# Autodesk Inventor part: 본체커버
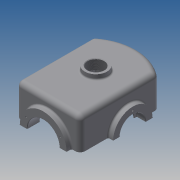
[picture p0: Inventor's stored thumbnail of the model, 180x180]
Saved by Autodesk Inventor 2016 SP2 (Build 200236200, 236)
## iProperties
Created: 2019-03
Part Number: 본체커버
Material: 알루미늄 6061
Document SubType Name: Modeling
Designer: mduedu
Density: 2.71 g/cm^3
Mass: 1472.73 g
Surface Area: 1101.4 cm^2
Volume: 543.443 cm^3
Appearance: 기본값
Author: mduedu
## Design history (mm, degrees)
sketch "스케치1"
  geometry: L1 (90, -65)-(-65.993, -65); L2 (-65.993, 65)-(90, 65); L3 (90, 65)-(90, -65); L4 (-90, 0)-(90, 0); A1 r 100 centre (10, 0) between (-65.993, 65) and (-65.993, -65); 2 further points
  constraints: 8 end point, 3 point on circle, 2 horizontal alignment, 2 midpoint, 1 centre point, 1 coincident, 1 horizontal, 1 parallel, 1 perpendicular
  dimensions: "d0" = 100 radius of A1; "d2" = 180 distance from line of L3 L4.start; "d3" = 130 distance between parallel lines of L2 L1
extrude "돌출1" new body sketch "스케치1" distance "d4" = 65; taper "d5" = 0 deg
fillet "모깎기1" dims "d6" = 10
fillet "모깎기2" dims "d7" = 10
feature "쉘1" dims "d8" = 10, "d79" = 15
fillet "모깎기3" dims "d9" = 3
fillet "모깎기4" dims "d10" = 3
sketch "스케치2"
  geometry: L1 (110, 0)-(0, 0) reference; A1 r 47.5 centre (55, 0) between (102.5, 0) and (7.5, 0); 1 further point
  constraints: 2 point on circle, 2 point on line, 1 centre point, 1 coincident
  dimensions: "d11" = 95 diameter of A1
extrude "돌출2" join sketch "스케치2" distance "d12" = 10; taper "d13" = 0 deg
hole "구멍1" diameter "d16" = 65; stored, may be unused: countersink angle "d20" = 90 deg, drill point angle "d22" = 118 deg; dims "d14" = 10, "d15" = 10, "d17" = 6, "d18" = 4, "d19" = 2, "d21" = 8
node "작업 평면1"
sketch "스케치3"
  geometry: L1 (61.239, 0)-(-80, 0) reference; L2 (-100, 47.5)-(-100, 0) reference; A1 r 40 centre (7, 0) between (47, 0) and (-33, 0); 1 further point
  constraints: 2 point on circle, 2 point on line, 1 centre point, 1 horizontal alignment
  dimensions: "d24" = 80 diameter of A1; "d25" = 107 distance from line of A1.centre L2
extrude "돌출3" join sketch "스케치3" stored distance "d26" = 10; taper "d27" = 0 deg
hole "구멍2" diameter "d30" = 42; stored, may be unused: countersink angle "d34" = 90 deg, drill point angle "d36" = 118 deg; dims "d28" = 10, "d29" = 10, "d31" = 6, "d32" = 52, "d33" = 18, "d35" = 8
sketch "스케치4" dims "d37" = 65
  geometry: A1 r 40 centre (7, 0) between (47, 0) and (-33, 0) reference; 3 further points
  constraints: 2 vertical alignment, 1 coincident, 2 other
hole "구멍3" sketch "스케치4" at (7, 32.5) diameter "d38" = 3.242; stored, may be unused: countersink angle "d42" = 90 deg, drill point angle "d44" = 118 deg; dims "d39" = 11, "d40" = 52, "d41" = 18, "d43" = 13
sketch "스케치5" dims "d45" = 80
  geometry: A1 r 47.5 centre (55, 0) between (102.5, 0) and (7.5, 0) reference; 5 further points
  constraints: 2 vertical alignment, 1 coincident, 6 other
  dimensions: "d48" = 360 deg dimension on point (55, 0) point (55, -40) (derived)
hole "구멍4" sketch "스케치5" at (55, -40), (89.641, 20), (20.359, 20) diameter "d50" = 3.242; stored, may be unused: countersink angle "d54" = 90 deg, drill point angle "d56" = 118 deg; dims "d51" = 11, "d52" = 52, "d53" = 18, "d55" = 13
fillet "모깎기5" dims "d57" = 3
fillet "모깎기6" dims "d58" = 1
chamfer "모따기1" distance "d59" = 1; stored, may be unused: second distance "d60" = 2, angle "d61" = 45 deg
node "작업 평면2"
sketch "스케치6"
  geometry: L1 (-47, 75)-(33, 75) reference; L2 (-47, -75)-(33, -75) reference; L3 (-7, 75)-(-7, -75); C1 r 22.5 at (-7, 0); 1 further point
  constraints: 3 midpoint, 2 end point, 1 centre point
  dimensions: "d63" = 45 diameter of C1
extrude "돌출4" join sketch "스케치6" stored distance "d64" = 10; taper "d65" = 0 deg
hole "구멍5" diameter "d68" = 33.376; stored, may be unused: countersink angle "d72" = 90 deg, drill point angle "d74" = 118 deg; dims "d66" = 10, "d67" = 10, "d69" = 11, "d70" = 52, "d71" = 18, "d73" = 13
fillet "모깎기7" dims "d75" = 3
chamfer "모따기2" distance "d76" = 1; stored, may be unused: second distance "d77" = 2, angle "d78" = 45 deg
node "솔리드1"
mirror "대칭1"
other parameters: "d23" = 75, "d62" = 75
